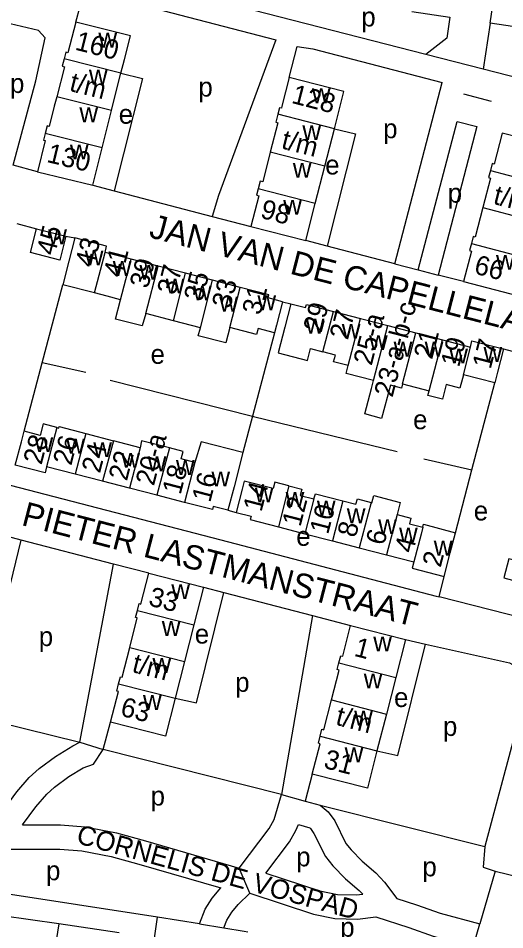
# Model space of a CAD drawing. Extents: x 163012 to 165277, y 382513 to 383987.
# Drawn here: x 164071.5 to 164172.1, y 383079.5 to 383268.2 of the extents above; entities that cross this region are included whole.
import ezdxf

# ---------------------------------------------------------------- set-up
doc = ezdxf.new("R2010")
doc.units = 0
for name, color, linetype in [('BLT_Basislijn', 7, 'Continuous'), ('BLT_Bebouwing', 7, 'Continuous'), ('BLT_Centroide', 7, 'Continuous'), ('BLT_Huisnummer', 7, 'Continuous'), ('BLT_Huisnummer_ tussenligend', 7, 'Continuous'), ('BLT_Huisnummer_reeks', 7, 'Continuous'), ('BLT_Onderverdeling_panden', 7, 'Continuous'), ('BLT_Straatnaam', 7, 'Continuous'), ('BLT_Straatnaam_verkleind', 7, 'Continuous'), ('BLT_Vlakafsluiter', 7, 'Continuous')]:
    doc.layers.add(name, color=color, linetype=linetype)

msp = doc.modelspace()

# ---------------------------------------------------------------- linework, layer by layer
at = {"layer": 'BLT_Basislijn'}
for p, q in [((164169.07, 383267.19), (164167.66, 383257.68)), ((164149.34, 383217.39), (164159.18, 383254.9)), ((164169.34, 383251), (164163.65, 383252.52)), ((164154.17, 383216.12), (164162.24, 383246.86)), ((164162.24, 383246.86), (164166.3, 383245.8)), ((164075.46, 383236.44), (164070.44, 383237.8)), ((164086.89, 383233.67), (164091.32, 383232.5)), ((164091.32, 383232.5), (164111.58, 383227.18)), ((164071.15, 383225.69), (164075.27, 383224.63)), ((164111.58, 383227.18), (164119.58, 383225.07)), ((164081.31, 383223.07), (164083.2, 383222.74)), ((164135.34, 383221.02), (164130.92, 383222.17)), ((164149.34, 383217.39), (164135.34, 383221.02)), ((164149.34, 383217.39), (164154.17, 383216.12)), ((164154.17, 383216.12), (164158.33, 383215.06)), ((164163.56, 383213.7), (164158.33, 383215.06)), ((164076.4, 383196.87), (164080.69, 383213.05)), ((164126.14, 383209.53), (164127.84, 383209.09)), ((164124.47, 383203.09), (164119.93, 383185.84)), ((164171.86, 383199.75), (164185.27, 383196.1)), ((164072.66, 383182.73), (164076.4, 383196.87)), ((164085.45, 383194.88), (164076.4, 383196.87)), ((164090.49, 383193.28), (164119.93, 383185.84)), ((164165.31, 383174.72), (164170.04, 383192.73)), ((164119.93, 383185.84), (164117.93, 383178.3)), ((164155.38, 383176.98), (164165.31, 383174.72)), ((164161.89, 383161.72), (164165.31, 383174.72)), ((164072.09, 383160.18), (164067.74, 383161.32)), ((164091.15, 383155.22), (164072.09, 383160.18)), ((164098.45, 383153.31), (164091.15, 383155.22)), ((164158.52, 383148.46), (164159.55, 383152.68)), ((164109.76, 383150.44), (164114.01, 383149.34)), ((164114.01, 383149.34), (164132.33, 383144.57)), ((164132.33, 383144.57), (164140.21, 383142.52)), ((164151.58, 383139.6), (164155.69, 383138.68)), ((164047.15, 383127.47), (164084.2, 383118.34)), ((164084.2, 383118.34), (164089.03, 383116.84)), ((164125.92, 383107.56), (164089.03, 383116.84)), ((164125.92, 383107.56), (164130.8, 383106.12)), ((164130.8, 383106.12), (164133.88, 383105.35)), ((164133.88, 383105.35), (164168, 383096.77)), ((164168, 383096.77), (164167.6, 383092.51)), ((164167.6, 383092.51), (164170.1, 383091.69)), ((164170.1, 383091.69), (164174.95, 383090.47)), ((164100.25, 383082.11), (164061.52, 383088.14)), ((164079.84, 383080.73), (164068.12, 383082.44)), ((164079.84, 383080.73), (164075.5, 383052.57)), ((164092.36, 383078.91), (164079.84, 383080.73)), ((164099.65, 383077.82), (164100.25, 383082.11)), ((164108.97, 383080.79), (164100.25, 383082.11)), ((164108.97, 383080.79), (164114, 383079.94))]:
    msp.add_line(p, q, dxfattribs=at)
for points in [[(164155.76, 383260.73), (164092.57, 383276.96)], [(164083.37, 383267.42), (164085.17, 383274.12), (164124.74, 383263.73), (164112.9, 383231.51), (164111.58, 383227.18)], [(164152.84, 383269.58), (164160.76, 383268.4), (164160.11, 383264.06), (164155.76, 383260.73)], [(164070.44, 383237.8), (164075.08, 383255.26), (164077.06, 383264.18), (164075.63, 383265.66), (164068.62, 383267.34)], [(164127.52, 383255.92), (164129.15, 383262.39), (164132.42, 383261.86), (164159.18, 383254.9)], [(164167.66, 383257.68), (164155.76, 383260.73)], [(164092.71, 383256.83), (164097.14, 383255.76), (164091.32, 383232.5)], [(164281.32, 383242.91), (164264.6, 383232.79), (164167.66, 383257.68)], [(164136.85, 383245.32), (164141.23, 383244.26), (164135.34, 383221.02)], [(164119.93, 383185.84), (164120.15, 383185.78), (164149.82, 383178.54)], [(164069.82, 383171.57), (164113.37, 383160.21), (164157.92, 383148.61), (164158.52, 383148.46)], [(164061.81, 383138.29), (164066.42, 383137.15), (164072.09, 383160.18)], [(164084.2, 383118.34), (164091.15, 383155.22)], [(164103.93, 383127.45), (164108.3, 383126.5), (164114.01, 383149.34)], [(164182.4, 383147), (164180.48, 383143.32), (164179.62, 383143.05), (164158.52, 383148.46)], [(164132.33, 383144.57), (164125.92, 383107.56)], [(164145.66, 383116.56), (164149.95, 383115.58), (164155.69, 383138.68)], [(164155.69, 383138.68), (164173.1, 383134.8), (164175.07, 383133.67), (164176.28, 383132.01), (164176.6, 383128.98), (164168, 383096.77)], [(164089.03, 383116.84), (164090.57, 383122.51)], [(164066.49, 383100.87), (164068.14, 383103.91), (164071.2, 383108.11), (164073.75, 383111.08), (164075.77, 383112.93), (164079.14, 383115.42), (164082.75, 383117.6), (164084.2, 383118.34)], [(164072.37, 383101.23), (164075.12, 383105.01), (164077.34, 383107.59), (164078.95, 383109.06), (164081.93, 383111.26), (164084.88, 383113.05), (164087.02, 383113.79), (164089.03, 383116.84)], [(164132.28, 383111.74), (164130.8, 383106.12)], [(164117.17, 383092.31), (164123.39, 383100.46), (164124.43, 383102.33), (164125.92, 383107.56)], [(164133.88, 383105.35), (164135.6, 383103.92), (164136.92, 383102.05), (164139.24, 383097.41), (164140.3, 383096.07), (164142.59, 383093.76), (164145.43, 383091.31), (164147.25, 383089.39), (164149.76, 383086.03)], [(164072.37, 383101.23), (164080.23, 383101.23), (164085.3, 383100.82), (164091.79, 383099.59), (164097.77, 383097.93), (164117.17, 383092.31)], [(164122.66, 383091.27), (164127.59, 383097.72), (164128.91, 383100.1), (164129.44, 383101.3)], [(164129.44, 383101.3), (164131.76, 383100.6), (164131.9, 383100.49), (164132.62, 383099.47), (164135, 383094.72), (164136.54, 383092.75), (164139.18, 383090.09), (164141.98, 383087.69), (164142.72, 383086.9)], [(164068.64, 383096.23), (164080.03, 383096.23), (164084.63, 383095.86), (164090.66, 383094.71), (164096.41, 383093.12), (164113.34, 383088.22)], [(164170.1, 383091.69), (164166.97, 383080.79)], [(164122.66, 383091.27), (164133.84, 383087.6), (164137.51, 383086.85), (164141.38, 383086.74), (164142.72, 383086.9)], [(164108.97, 383080.79), (164110.09, 383083.76), (164111.56, 383086.09), (164113.34, 383088.22)], [(164114, 383079.94), (164114.59, 383081.53), (164115.61, 383083.14), (164116.94, 383084.74), (164119.33, 383087.1)], [(164119.33, 383087.1), (164132.55, 383082.76), (164136.93, 383081.86), (164141.61, 383081.73), (164145.42, 383082.19)], [(164149.76, 383086.03), (164153.83, 383084.71), (164158.74, 383082.96), (164166.97, 383080.79)], [(164145.42, 383082.19), (164152.22, 383079.97), (164157.27, 383078.18), (164165.59, 383075.99)], [(164114, 383079.94), (164118.18, 383079.24), (164118.98, 383079.12)]]:
    msp.add_lwpolyline(points, dxfattribs=at)
at = {"layer": 'BLT_Bebouwing'}
for p, q in [((164090.97, 383250), (164092.71, 383256.83)), ((164127.52, 383255.92), (164126.01, 383250)), ((164079.41, 383251.97), (164078.91, 383250)), ((164088.82, 383241.39), (164090.74, 383249.11)), ((164090.74, 383249.11), (164090.97, 383250)), ((164136.85, 383245.32), (164138.05, 383250)), ((164134.88, 383237.6), (164136.85, 383245.32)), ((164086.89, 383233.67), (164088.82, 383241.39)), ((164132.9, 383229.89), (164134.88, 383237.6)), ((164075.46, 383236.44), (164086.89, 383233.67)), ((164130.92, 383222.17), (164132.9, 383229.89)), ((164119.58, 383225.07), (164130.92, 383222.17)), ((164094.8, 383218.35), (164089.42, 383219.75)), ((164100.4, 383216.9), (164094.8, 383218.35)), ((164106.09, 383215.43), (164100.4, 383216.9)), ((164111.67, 383213.98), (164106.09, 383215.43)), ((164087.24, 383211.35), (164080.69, 383213.05)), ((164117.39, 383212.5), (164111.67, 383213.98)), ((164163.56, 383213.7), (164174.96, 383210.74)), ((164103.55, 383205.6), (164097.86, 383207.07)), ((164136.65, 383207.52), (164142.25, 383206.06)), ((164142.25, 383206.06), (164147.92, 383204.59)), ((164147.92, 383204.59), (164153.68, 383203.1)), ((164153.68, 383203.1), (164159.21, 383201.67)), ((164159.21, 383201.67), (164165.04, 383200.15)), ((164170.04, 383192.73), (164163.54, 383194.39)), ((164150.95, 383192.56), (164156.46, 383191.08)), ((164085.43, 383182.24), (164091.13, 383180.74)), ((164096.65, 383179.31), (164091.13, 383180.74)), ((164077, 383174.1), (164070.84, 383175.69)), ((164077.33, 383175.37), (164077, 383174.1)), ((164083.25, 383173.84), (164077.33, 383175.37)), ((164088.88, 383172.38), (164083.25, 383173.84)), ((164094.48, 383170.93), (164088.88, 383172.38)), ((164100.16, 383169.46), (164094.48, 383170.93)), ((164105.85, 383167.99), (164100.16, 383169.46)), ((164114.83, 383166.36), (164116.55, 383165.91)), ((164125.26, 383162.91), (164130.72, 383161.5)), ((164130.72, 383161.5), (164136.48, 383160.01)), ((164136.48, 383160.01), (164141.99, 383158.59)), ((164141.99, 383158.59), (164147.66, 383157.12)), ((164147.66, 383157.12), (164153.28, 383155.66)), ((164153.28, 383155.66), (164152.95, 383154.39)), ((164152.95, 383154.39), (164159.55, 383152.68)), ((164098.45, 383153.31), (164109.76, 383150.44)), ((164109.76, 383150.44), (164107.79, 383142.65)), ((164107.79, 383142.65), (164105.86, 383135.07)), ((164140.21, 383142.52), (164151.58, 383139.6)), ((164151.58, 383139.6), (164149.57, 383131.78)), ((164105.86, 383135.07), (164103.93, 383127.45)), ((164149.57, 383131.78), (164147.61, 383124.17)), ((164147.61, 383124.17), (164145.66, 383116.56))]:
    msp.add_line(p, q, dxfattribs=at)
for points in [[(164169.07, 383267.19), (164172.05, 383287.2)], [(164083.37, 383267.42), (164081.75, 383261.07), (164081.31, 383261.18), (164080.95, 383259.79)], [(164092.71, 383256.83), (164093.44, 383259.69), (164094.68, 383264.54), (164083.37, 383267.42)], [(164278.85, 383251.93), (164240.91, 383245.53), (164236.46, 383261.46), (164226.4, 383258.64), (164169.07, 383267.19)], [(164080.95, 383259.79), (164080.57, 383258.29), (164081, 383258.18), (164079.41, 383251.97)], [(164138.05, 383250), (164138.83, 383253.03), (164127.52, 383255.92)], [(164078.91, 383250), (164077.88, 383245.83), (164077.42, 383245.94), (164077.04, 383244.36)], [(164125.14, 383248.32), (164124.72, 383246.7), (164125.14, 383246.59), (164123.58, 383240.49)], [(164126.01, 383250), (164125.91, 383249.58), (164125.48, 383249.68), (164125.14, 383248.32)], [(164166.3, 383245.8), (164158.33, 383215.06)], [(164077.04, 383244.36), (164076.7, 383242.98), (164077.02, 383242.9), (164075.46, 383236.44)], [(164171.57, 383244.43), (164169.9, 383238.02), (164169.49, 383238.13), (164169.11, 383236.67)], [(164182.93, 383241.49), (164171.57, 383244.43)], [(164123.58, 383240.49), (164122.02, 383234.37), (164121.52, 383234.5), (164121.11, 383232.91)], [(164169.11, 383236.67), (164168.73, 383235.21), (164169.14, 383235.1), (164167.56, 383229)], [(164121.11, 383232.91), (164120.76, 383231.57), (164121.22, 383231.45), (164119.58, 383225.07)], [(164167.56, 383229), (164165.98, 383222.9), (164165.56, 383223.01), (164165.18, 383221.56)], [(164081.31, 383223.07), (164080.03, 383218.16), (164074, 383219.73), (164075.27, 383224.63)], [(164075.27, 383224.63), (164081.31, 383223.07)], [(164083.2, 383222.74), (164081.95, 383217.9), (164080.69, 383213.05)], [(164089.42, 383219.75), (164089.75, 383221.04), (164083.2, 383222.74)], [(164165.18, 383221.56), (164164.8, 383220.11), (164165.19, 383220.01), (164163.56, 383213.7)], [(164126.14, 383209.53), (164123.14, 383210.3), (164123.31, 383210.97), (164117.39, 383212.5)], [(164092.63, 383209.95), (164089.83, 383210.67), (164087.24, 383211.35)], [(164097.86, 383207.07), (164097.11, 383204.54), (164091.6, 383205.94), (164092.63, 383209.95)], [(164126.14, 383209.53), (164124.89, 383204.69), (164124.47, 383203.09)], [(164127.84, 383209.09), (164126.58, 383204.25), (164125.2, 383198.92), (164131.3, 383197.34), (164131.94, 383199.82), (164134.48, 383199.16)], [(164127.84, 383209.09), (164130.88, 383208.3), (164131.05, 383208.97), (164136.65, 383207.52)], [(164109.13, 383204.15), (164103.55, 383205.6)], [(164115.23, 383204.17), (164114.41, 383201.01), (164108.7, 383202.49), (164109.13, 383204.15)], [(164124.47, 383203.09), (164121.07, 383203.97), (164120.75, 383202.74), (164115.23, 383204.17)], [(164165.04, 383200.15), (164165.28, 383201.46), (164171.86, 383199.75)], [(164171.86, 383199.75), (164170.61, 383194.92), (164170.04, 383192.73)], [(164139.73, 383196.3), (164136.7, 383197.09), (164137.07, 383198.49), (164134.48, 383199.16)], [(164144.96, 383193.19), (164139.31, 383194.65), (164139.73, 383196.3)], [(164163.54, 383194.39), (164163.35, 383193.64), (164162.83, 383191.65), (164159.99, 383192.38), (164159.21, 383189.36), (164156.21, 383190.13), (164156.46, 383191.08)], [(164150.95, 383192.56), (164150.71, 383191.62), (164148.44, 383192.26), (164146.61, 383185.39), (164143.17, 383186.29), (164144.54, 383191.57), (164144.96, 383193.19)], [(164079.43, 383183.49), (164076.61, 383184.24), (164075.99, 383181.86), (164072.66, 383182.73)], [(164070.84, 383175.69), (164072.1, 383180.53), (164072.66, 383182.73)], [(164079.43, 383183.49), (164079.86, 383183.39), (164079.93, 383183.67), (164085.43, 383182.24)], [(164102.72, 383179.27), (164096.97, 383180.76), (164096.65, 383179.31)], [(164117.93, 383178.3), (164109.28, 383180.54), (164107.99, 383176.25)], [(164107.99, 383176.25), (164105.18, 383176.98), (164105.58, 383178.52), (164102.72, 383179.27)], [(164117.93, 383178.3), (164116.09, 383171.21), (164114.83, 383166.36)], [(164127.45, 383171.41), (164124.52, 383172.16), (164124.19, 383170.88), (164118.22, 383172.36), (164117.8, 383170.75), (164116.55, 383165.91)], [(164127.45, 383171.41), (164130.11, 383170.72), (164129.78, 383169.44), (164132.58, 383168.71)], [(164132.58, 383168.71), (164132.93, 383169.79), (164138.62, 383168.31)], [(164144.46, 383167.96), (164144.61, 383167.92), (164145, 383169.4), (164150.47, 383167.98), (164149.82, 383165.47)], [(164114.83, 383166.36), (164111.8, 383167.15), (164111.63, 383166.49), (164105.85, 383167.99)], [(164138.62, 383168.31), (164141.32, 383167.61), (164141.61, 383168.7), (164144.46, 383167.96)], [(164116.55, 383165.91), (164119.61, 383165.12), (164119.43, 383164.42), (164125.26, 383162.91)], [(164149.82, 383165.47), (164152.68, 383164.74), (164152.38, 383163.57), (164155.14, 383162.86)], [(164155.14, 383162.86), (164155.3, 383163.48), (164161.89, 383161.72)], [(164159.55, 383152.68), (164160.8, 383157.52), (164161.89, 383161.72)], [(164174.58, 383155.9), (164172.91, 383156.34), (164171.88, 383152.36), (164176.51, 383151.15), (164175.87, 383148.7), (164182.4, 383147)], [(164096.1, 383145.61), (164096.47, 383147.05), (164096.84, 383146.95), (164098.45, 383153.31)], [(164094.51, 383137.95), (164096.07, 383144.09), (164095.74, 383144.17), (164096.1, 383145.61)], [(164137.8, 383134.8), (164138.17, 383136.24), (164138.57, 383136.13), (164140.21, 383142.52)], [(164092.21, 383130.42), (164092.59, 383131.9), (164092.96, 383131.81), (164094.51, 383137.95)], [(164136.24, 383127.09), (164137.83, 383133.26), (164137.43, 383133.37), (164137.8, 383134.8)], [(164090.57, 383122.51), (164092.18, 383128.85), (164091.84, 383128.94), (164092.21, 383130.42)], [(164103.93, 383127.45), (164101.95, 383119.62), (164090.57, 383122.51)], [(164133.92, 383119.57), (164134.29, 383121.02), (164134.66, 383120.92), (164136.24, 383127.09)], [(164132.28, 383111.74), (164133.9, 383118.04), (164133.55, 383118.13), (164133.92, 383119.57)], [(164145.66, 383116.56), (164143.67, 383108.81), (164132.28, 383111.74)]]:
    msp.add_lwpolyline(points, dxfattribs=at)
at = {"layer": 'BLT_Onderverdeling_panden'}
for p, q in [((164092.71, 383256.83), (164080.95, 383259.79)), ((164090.74, 383249.11), (164079.41, 383251.97)), ((164136.85, 383245.32), (164125.14, 383248.32)), ((164088.82, 383241.39), (164077.04, 383244.36)), ((164134.88, 383237.6), (164123.58, 383240.49)), ((164169.11, 383236.67), (164180.89, 383233.61)), ((164132.9, 383229.89), (164121.11, 383232.91)), ((164167.56, 383229), (164178.93, 383226.05)), ((164165.18, 383221.56), (164176.97, 383218.5)), ((164087.24, 383211.35), (164089.42, 383219.75)), ((164092.63, 383209.95), (164094.8, 383218.35)), ((164097.86, 383207.07), (164100.4, 383216.9)), ((164103.55, 383205.6), (164106.09, 383215.43)), ((164109.13, 383204.15), (164111.67, 383213.98)), ((164115.23, 383204.17), (164117.39, 383212.5)), ((164134.48, 383199.16), (164136.65, 383207.52)), ((164139.73, 383196.3), (164142.25, 383206.06)), ((164144.96, 383193.19), (164147.92, 383204.59)), ((164150.95, 383192.56), (164153.68, 383203.1)), ((164156.46, 383191.08), (164159.21, 383201.67)), ((164163.54, 383194.39), (164165.04, 383200.15)), ((164079.43, 383183.49), (164077.33, 383175.37)), ((164085.43, 383182.24), (164083.25, 383173.84)), ((164091.13, 383180.74), (164088.88, 383172.38)), ((164096.65, 383179.31), (164094.48, 383170.93)), ((164102.72, 383179.27), (164100.16, 383169.46)), ((164107.99, 383176.25), (164105.85, 383167.99)), ((164127.45, 383171.41), (164125.26, 383162.91)), ((164132.58, 383168.71), (164130.72, 383161.5)), ((164138.62, 383168.31), (164136.48, 383160.01)), ((164144.46, 383167.96), (164141.99, 383158.59)), ((164149.82, 383165.47), (164147.66, 383157.12)), ((164096.1, 383145.61), (164107.79, 383142.65)), ((164094.51, 383137.95), (164105.86, 383135.07)), ((164137.8, 383134.8), (164149.57, 383131.78)), ((164092.21, 383130.42), (164103.93, 383127.45)), ((164136.24, 383127.09), (164147.61, 383124.17)), ((164133.92, 383119.57), (164145.66, 383116.56))]:
    msp.add_line(p, q, dxfattribs=at)
msp.add_lwpolyline([(164155.14, 383162.86), (164154.77, 383161.42), (164153.28, 383155.66)], dxfattribs=at)
at = {"layer": 'BLT_Vlakafsluiter'}
for p, q in [((164119.33, 383087.1), (164117.17, 383092.31)), ((164165.59, 383075.99), (164166.97, 383080.79))]:
    msp.add_line(p, q, dxfattribs=at)

# ---------------------------------------------------------------- texts
at = {"layer": 'BLT_Centroide'}
for s, p in [('p', (164142.42, 383266.51)), ('w', (164088.04, 383262.12)), ('p', (164069.76, 383252.74)), ('w', (164086.08, 383254.47)), ('p', (164108.72, 383251.99)), ('w', (164132.2, 383250.62)), ('w', (164084.11, 383246.69)), ('e', (164092.24, 383246.37)), ('p', (164146.94, 383243.37)), ('w', (164130.23, 383242.97)), ('w', (164082.15, 383239)), ('e', (164134.95, 383235.87)), ('w', (164128.25, 383235.19)), ('p', (164160.29, 383230.03)), ('w', (164126.26, 383227.53)), ('w', (164077.66, 383221.41)), ('w', (164085.22, 383217.05)), ('w', (164170.27, 383216.16)), ('w', (164091.02, 383214.86)), ('w', (164096.52, 383214.09)), ('w', (164101.97, 383211.25)), ('w', (164107.61, 383209.8)), ('w', (164113.05, 383207.5)), ('w', (164120.93, 383207.78)), ('w', (164130.92, 383202.95)), ('w', (164138.38, 383201.86)), ('w', (164144.03, 383199.52)), ('w', (164149.11, 383198.16)), ('w', (164155.53, 383198.17)), ('e', (164098.83, 383196.68)), ('w', (164160.62, 383196.77)), ('w', (164167.7, 383197.08)), ('e', (164153.13, 383183.14)), ('w', (164074.83, 383178.41)), ('w', (164081.38, 383178.09)), ('w', (164086.98, 383177.36)), ('w', (164092.77, 383175.16)), ('w', (164098.23, 383174.44)), ('w', (164104.08, 383173.67)), ('w', (164111.41, 383171.31)), ('w', (164120.38, 383168)), ('w', (164126.77, 383167.06)), ('w', (164133.23, 383165.28)), ('e', (164165.68, 383164.26)), ('w', (164139.42, 383163.67)), ('w', (164145.91, 383161.42)), ('e', (164128.96, 383159.01)), ('w', (164150.23, 383159.7)), ('w', (164157.41, 383156.97)), ('w', (164103.12, 383147.97)), ('w', (164101.16, 383140.34)), ('p', (164075.71, 383138.25)), ('e', (164107.98, 383138.77)), ('w', (164144.89, 383137.16)), ('w', (164099.23, 383132.69)), ('p', (164116.33, 383128.78)), ('w', (164142.92, 383129.5)), ('w', (164097.26, 383125.03)), ('e', (164149.19, 383125.64)), ('w', (164140.95, 383121.81)), ('p', (164159.31, 383119.65)), ('w', (164138.98, 383114.19)), ('p', (164098.84, 383105.24)), ('p', (164128.95, 383092.65)), ('p', (164155.06, 383090.59)), ('p', (164077.21, 383089.78)), ('p', (164138.06, 383078.09))]:
    msp.add_text(s, height=4, dxfattribs=at).set_placement(p)
at = {"layer": 'BLT_Huisnummer'}
for s, rotation, p in [('45', 75.4785, (164078.99, 383218.92)), ('43', 75.4755, (164086.99, 383216.45)), ('39', 75.4689, (164098.28, 383212.11)), ('35', 75.4729, (164109.49, 383209.41)), ('31', 75.4606, (164121.53, 383206.59)), ('29', 75.4663, (164134.19, 383203)), ('21', 75.4655, (164157.05, 383197.43)), ('17', 75.3855, (164169.16, 383195.42)), ('28', 75.5013, (164076.28, 383175.64)), ('24', 75.4966, (164088.35, 383173.89)), ('16', 75.4775, (164111.16, 383167.84)), ('14', 75.4953, (164121.76, 383165.88)), ('10', 75.4986, (164135.54, 383161.22)), ('6', 75.5001, (164147.13, 383158.94)), ('2', 75.491, (164158.82, 383154.38))]:
    msp.add_text(s, height=4, rotation=rotation, dxfattribs=at).set_placement(p)
at = {"layer": 'BLT_Huisnummer_ tussenligend'}
for s, rotation, p in [('41', 75.4689, (164092.85, 383214.34)), ('37', 75.4729, (164103.94, 383210.78)), ('33', 75.4606, (164115.28, 383207.93)), ('27', 75.4586, (164139.63, 383201.47)), ('19', 75.3855, (164162.63, 383195.82)), ('26', 75.4966, (164082.42, 383175.48)), ('22', 75.5029, (164093.93, 383172.29)), ('18', 75.4775, (164105.03, 383169.44)), ('12', 75.4986, (164129.82, 383162.8)), ('8', 75.5001, (164141.25, 383160.55)), ('4', 75.491, (164153.08, 383157.33))]:
    msp.add_text(s, height=4, rotation=rotation, dxfattribs=at).set_placement(p)
at = {"layer": 'BLT_Huisnummer_reeks'}
for s, rotation, p in [('160', 345.8425, (164083.02, 383261.73)), ('t/m', 345.8417, (164081.86, 383253.22)), ('128', 345.6318, (164127.8, 383250.7)), ('t/m', 345.6312, (164125.68, 383241.32)), ('130', 346.3677, (164077.17, 383238.49)), ('t/m', 345.4596, (164169.52, 383229.84)), ('98', 345.6539, (164121.36, 383226.93)), ('66', 345.461, (164165.55, 383215.41)), ('23-a-b-c', 75.4655, (164148.86, 383189.59)), ('25-a', 75.4586, (164144.55, 383196.16)), ('20-a', 75.5029, (164099.51, 383171.27)), ('33', 345.7696, (164098.22, 383146.7)), ('1', 345.5962, (164140.75, 383136.26)), ('t/m', 345.7637, (164094.81, 383132.92)), ('63', 345.7758, (164092.39, 383123.89)), ('t/m', 345.5935, (164136.92, 383122.01)), ('31', 345.5818, (164134.44, 383113.08))]:
    msp.add_text(s, height=4, rotation=rotation, dxfattribs=at).set_placement(p)
at = {"layer": 'BLT_Straatnaam'}
for s, rotation, p in [('JAN VAN DE CAPELLELAAN', 345.5262, (164098.31, 383222.9)), ('PIETER LASTMANSTRAAT', 345.4488, (164071.93, 383163.35))]:
    msp.add_text(s, height=5, rotation=rotation, dxfattribs=at).set_placement(p)
at = {"layer": 'BLT_Straatnaam_verkleind'}
msp.add_text('CORNELIS DE VOSPAD', height=4, rotation=344.5928, dxfattribs=at).set_placement((164083.27, 383097.52))

doc.saveas('drawing.dxf')
